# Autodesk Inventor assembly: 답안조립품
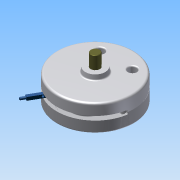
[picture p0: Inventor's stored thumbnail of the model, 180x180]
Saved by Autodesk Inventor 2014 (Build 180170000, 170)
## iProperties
Created: 2015-07
Part Number: 답안조립품
Document SubType Name: Assembly
Designer: Administrator
Author: Administrator
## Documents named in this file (10)
- C:\Documents and Settings\Administrator\바탕 화면\450631V1012\답안조립품.iam
- C:\Documents and Settings\Administrator\바탕 화면\450631V1012\본체.ipt
- C:\Documents and Settings\Administrator\바탕 화면\450631V1012\덮개.ipt
- C:\Documents and Settings\Administrator\바탕 화면\450631V1012\베어링62_22.ipt
- C:\Documents and Settings\Administrator\바탕 화면\450631V1012\축.ipt
- C:\Documents and Settings\Administrator\바탕 화면\450631V1012\평행핀.ipt
- C:\Documents and Settings\Administrator\바탕 화면\450631V1012\M10x35.ipt
- C:\Documents and Settings\Administrator\바탕 화면\450631V1012\멈춤링.ipt
- C:\Documents and Settings\Administrator\바탕 화면\450631V1012\슬라이더2.ipt
- C:\Documents and Settings\Administrator\바탕 화면\450631V1012\슬라이더.ipt
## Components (7 placed, 4 different names)
1. KS B 2023 62/22 - 22 x 50 x 14:1
2. KS B 2023 62/22 - 22 x 50 x 14:2
3. KS B 1320 B B 5 x  20:1
4. KS B 1003 - 미터 M 10 x 35:1
5. KS B 1336 22 x 1.2:1
6. KS B 1336 22 x 1.2:2
7. KS B 1003 - 미터 M 10 x 35:2
